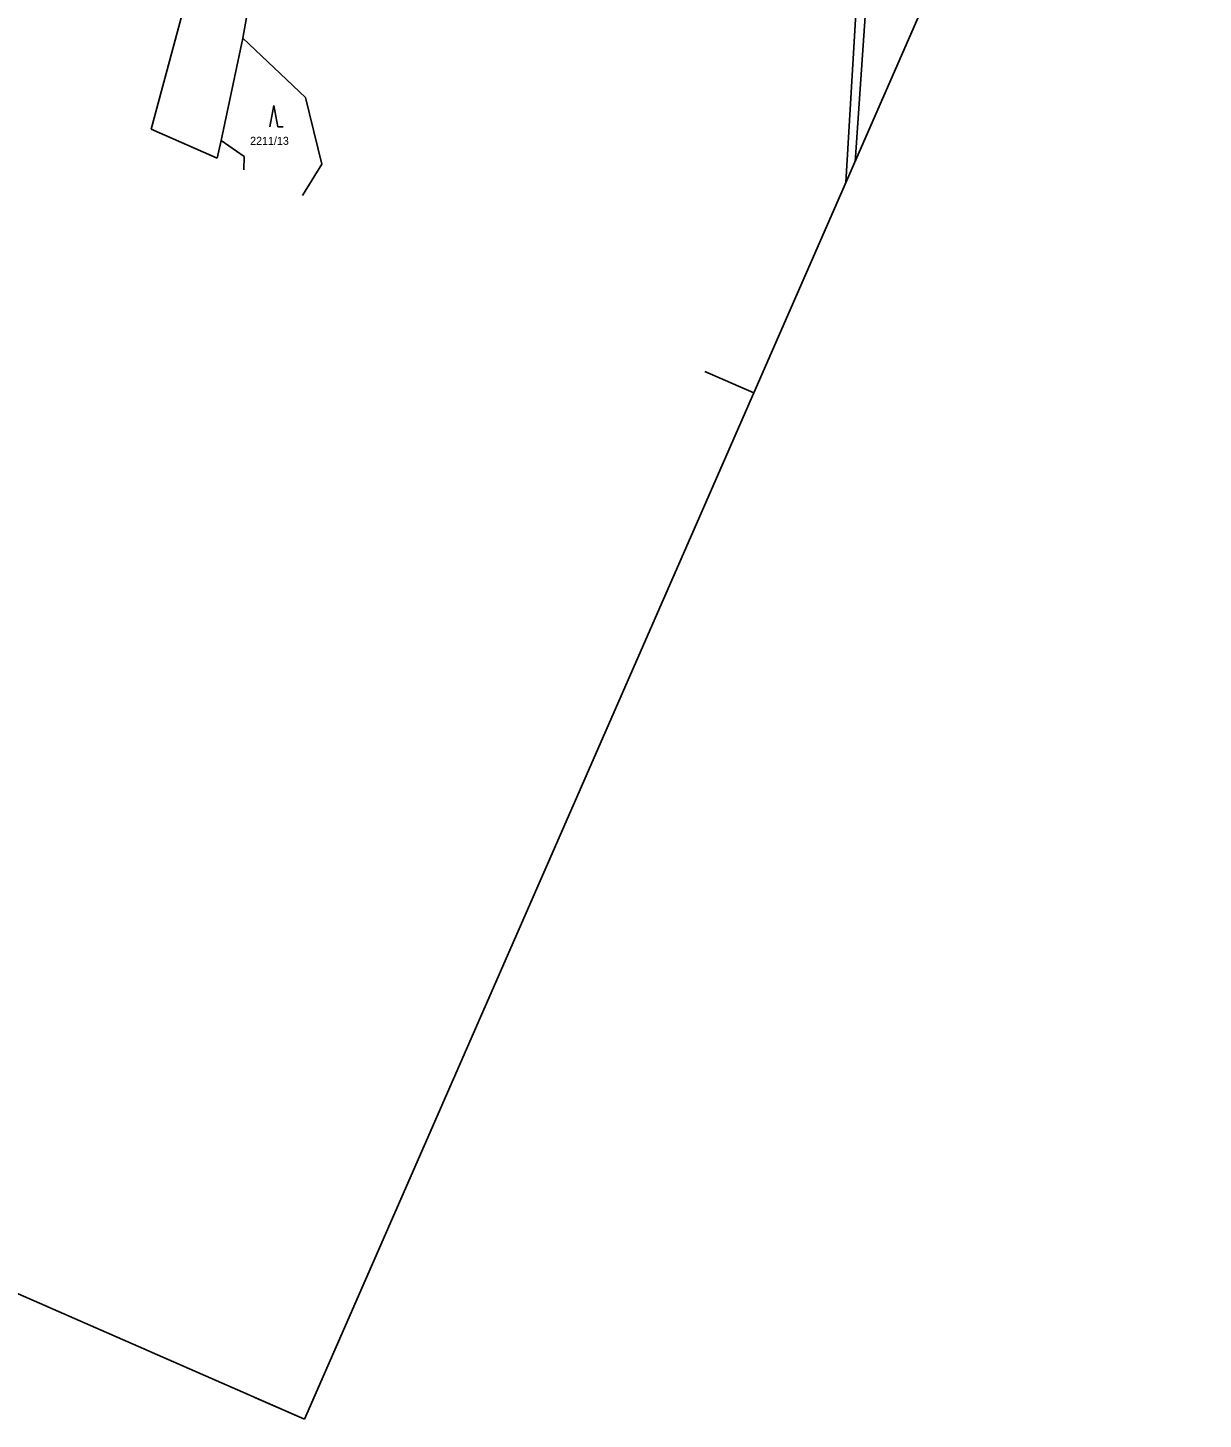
# Model space of a CAD drawing. Extents: x -806856 to -806332, y -1151642 to -1150946.
# Drawn here: x -806636.1 to -806415.8, y -1151642.4 to -1151381.6 of the extents above; entities that cross this region are included whole.
import ezdxf

# ---------------------------------------------------------------- set-up
doc = ezdxf.new("R2010")
doc.units = 0
for name, color, linetype in [('Default', 7, 'Continuous'), ('formát', 7, 'Continuous'), ('kn_celek - Cisla pozemkovych parcel', 7, 'Continuous'), ('kn_celek - Hranice parcel', 7, 'Continuous'), ('kn_celek - Vnitrni kresby', 7, 'Continuous'), ('kn_celek - Znacky kultur', 7, 'Continuous'), ('plochy - SZDC', 7, 'Continuous')]:
    doc.layers.add(name, color=color, linetype=linetype)

# ---------------------------------------------------------------- blocks, each defined once
blk = doc.blocks.new('308')
at = {"layer": 'Default'}
for p, q in [((-7.5, 0.2), (0, 40.2)), ((0, 40.2), (7.5, 0.2)), ((7.5, 0.2), (17.5, 0.2))]:
    blk.add_line(p, q, dxfattribs=at)

msp = doc.modelspace()

# ---------------------------------------------------------------- linework, layer by layer
at = {"layer": 'formát'}
for p, q in [((-806415.83, -1151257.68), (-806500.03, -1151450.06)), ((-806509.19, -1151446.05), (-806500.03, -1151450.06)), ((-806509.19, -1151446.05), (-806500.03, -1151450.06)), ((-806500.03, -1151450.06), (-806584.22, -1151642.44)), ((-806856.31, -1151523.36), (-806584.22, -1151642.44)), ((-806593.38, -1151638.43), (-806584.22, -1151642.44))]:
    msp.add_line(p, q, dxfattribs=at)
at = {"layer": 'kn_celek - Hranice parcel'}
for p, q in [((-806595.8, -1151383.59), (-806588.67, -1151342.95)), ((-806604.52, -1151369.36), (-806612.97, -1151400.63)), ((-806482.78, -1151410.66), (-806480.46, -1151370.89)), ((-806599.86, -1151402.77), (-806595.8, -1151383.59)), ((-806595.8, -1151383.59), (-806584.01, -1151394.69)), ((-806584.01, -1151394.69), (-806580.97, -1151407.19)), ((-806600.56, -1151406.06), (-806599.86, -1151402.77)), ((-806599.86, -1151402.77), (-806595.52, -1151405.73)), ((-806595.52, -1151405.73), (-806595.59, -1151408.24)), ((-806580.97, -1151407.19), (-806584.59, -1151413.05))]:
    msp.add_line(p, q, dxfattribs=at)
at = {"layer": 'kn_celek - Vnitrni kresby'}
msp.add_line((-806478.12, -1151364.73), (-806481.06, -1151406.74), dxfattribs=at)
at = {"layer": 'plochy - SZDC'}
for p, q in [((-806595.8, -1151383.59), (-806588.67, -1151342.95)), ((-806604.52, -1151369.36), (-806612.97, -1151400.63)), ((-806599.86, -1151402.77), (-806595.8, -1151383.59)), ((-806600.56, -1151406.06), (-806612.97, -1151400.63)), ((-806612.97, -1151400.63), (-806600.56, -1151406.06)), ((-806600.56, -1151406.06), (-806599.86, -1151402.77))]:
    msp.add_line(p, q, dxfattribs=at)

# ---------------------------------------------------------------- block references
at = {"layer": 'kn_celek - Znacky kultur', "xscale": 0.1, "yscale": 0.10000000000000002}
msp.add_blockref('308', (-806589.98, -1151400.23), dxfattribs=at)

# ---------------------------------------------------------------- texts
at = {"layer": 'kn_celek - Cisla pozemkovych parcel'}
msp.add_text('2211/13', height=1.5, dxfattribs=at).set_placement((-806594.41, -1151403.57))

doc.saveas('drawing.dxf')
